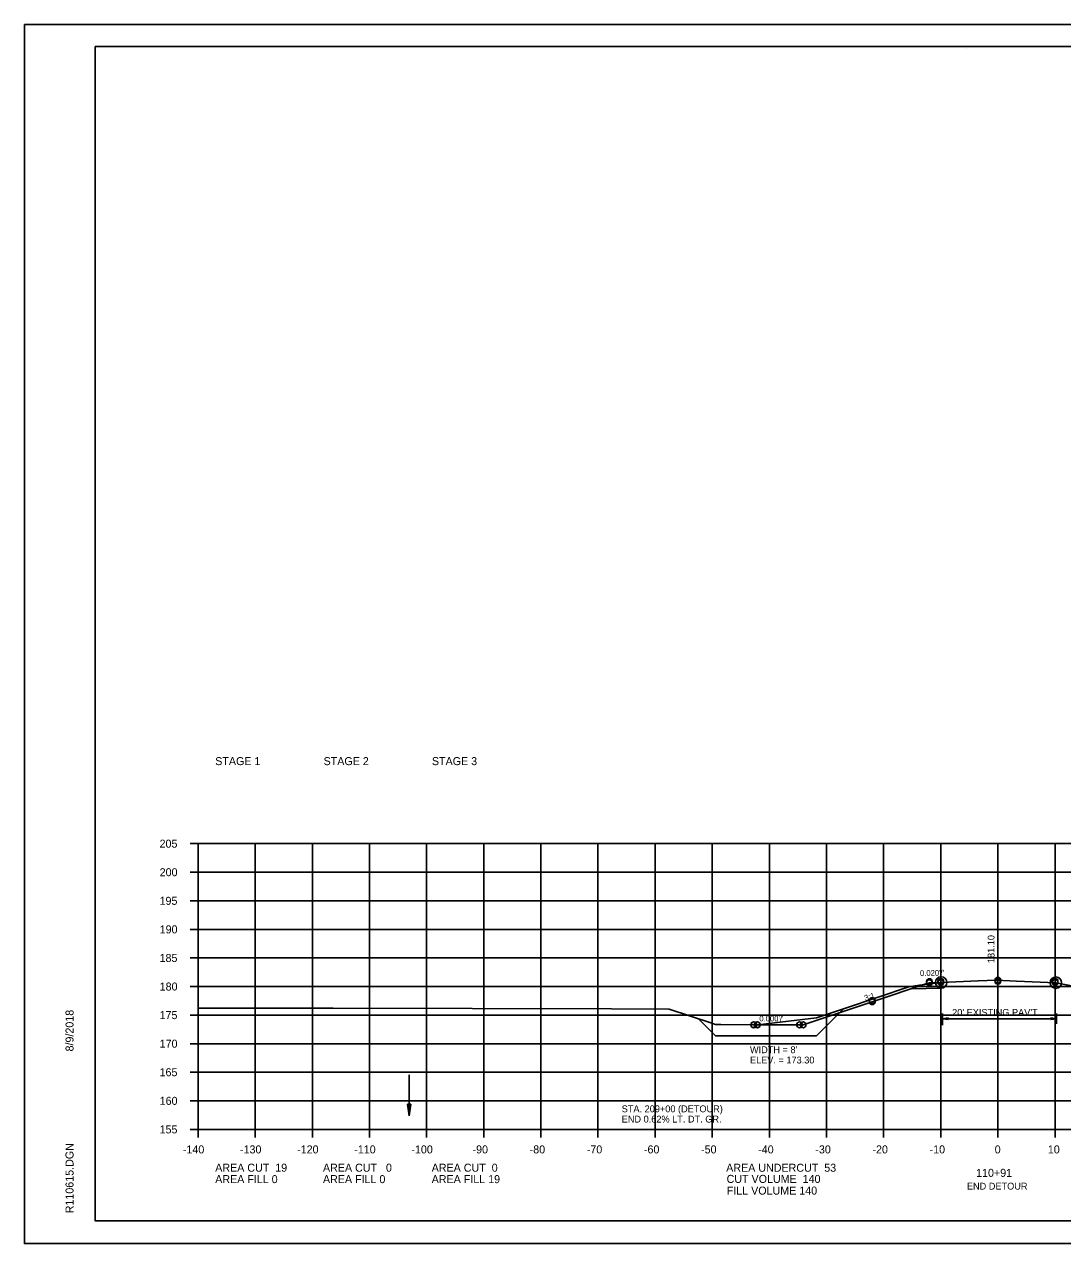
# Model space of a CAD drawing. Extents: x 1372132 to 1372465, y 380083 to 381790.
# Drawn here: x 1372131.6 to 1372313.3, y 381576.9 to 381790.2 of the extents above; entities that cross this region are included whole.
import ezdxf

# ---------------------------------------------------------------- set-up
doc = ezdxf.new("R2010")
doc.units = 0
for name, color, linetype in [('R_Alt Surface', 7, 'Continuous'), ('R_Axis', 7, 'Continuous'), ('R_Axis Annot', 7, 'Continuous'), ('R_Border', 7, 'Continuous'), ('R_Dimension', 7, 'Continuous'), ('R_Draft', 7, 'Continuous'), ('R_Erosion', 7, 'Continuous'), ('R_Exist Surface', 7, 'Continuous'), ('R_Fin Surface', 7, 'Continuous'), ('R_Grid', 7, 'Continuous'), ('R_No Plot', 7, 'Continuous'), ('R_Xsect Elev', 7, 'Continuous'), ('R_Xsect Slope', 7, 'Continuous')]:
    doc.layers.add(name, color=color, linetype=linetype)

msp = doc.modelspace()

# ---------------------------------------------------------------- linework, layer by layer
at = {"layer": 'R_Alt Surface'}
msp.add_lwpolyline([(1372292.07, 381621.55), (1372286.82, 381621.44)], dxfattribs=at)
at = {"layer": 'R_Axis'}
for p, q in [((1372160.61, 381646.84), (1372162.01, 381646.84)), ((1372162.01, 381596.84), (1372162.01, 381646.84)), ((1372160.61, 381641.84), (1372162.01, 381641.84)), ((1372160.61, 381636.84), (1372162.01, 381636.84)), ((1372160.61, 381631.84), (1372162.01, 381631.84)), ((1372160.61, 381626.84), (1372162.01, 381626.84)), ((1372160.61, 381621.84), (1372162.01, 381621.84)), ((1372160.61, 381616.84), (1372162.01, 381616.84)), ((1372160.61, 381611.84), (1372162.01, 381611.84)), ((1372160.61, 381606.84), (1372162.01, 381606.84)), ((1372160.61, 381601.84), (1372162.01, 381601.84)), ((1372160.61, 381596.84), (1372162.01, 381596.84)), ((1372162.01, 381596.84), (1372442.01, 381596.84)), ((1372162.01, 381595.44), (1372162.01, 381596.84)), ((1372172.01, 381595.44), (1372172.01, 381596.84)), ((1372182.01, 381595.44), (1372182.01, 381596.84)), ((1372192.01, 381595.44), (1372192.01, 381596.84)), ((1372202.01, 381595.44), (1372202.01, 381596.84)), ((1372212.01, 381595.44), (1372212.01, 381596.84)), ((1372222.01, 381595.44), (1372222.01, 381596.84)), ((1372232.01, 381595.44), (1372232.01, 381596.84)), ((1372242.01, 381595.44), (1372242.01, 381596.84)), ((1372252.01, 381595.44), (1372252.01, 381596.84)), ((1372262.01, 381595.44), (1372262.01, 381596.84)), ((1372272.01, 381595.44), (1372272.01, 381596.84)), ((1372282.01, 381595.44), (1372282.01, 381596.84)), ((1372292.01, 381595.44), (1372292.01, 381596.84)), ((1372302.01, 381595.44), (1372302.01, 381596.84)), ((1372312.01, 381595.44), (1372312.01, 381596.84))]:
    msp.add_line(p, q, dxfattribs=at)
at = {"layer": 'R_Border'}
for p, q in [((1372144.01, 381786.3), (1372460.19, 381786.3)), ((1372144.01, 381580.84), (1372144.01, 381786.3)), ((1372296.53, 381786.04), (1372296.53, 381786.04)), ((1372296.53, 381786.04), (1372296.53, 381786.04)), ((1372144.01, 381580.84), (1372144.01, 381580.84)), ((1372460.19, 381580.84), (1372144.01, 381580.84))]:
    msp.add_line(p, q, dxfattribs=at)
at = {"layer": 'R_Dimension'}
for p, q in [((1372198.64, 381601.24), (1372198.94, 381599.24)), ((1372199.24, 381601.24), (1372198.64, 381601.24)), ((1372198.64, 381601.24), (1372198.94, 381599.24)), ((1372199.24, 381601.24), (1372198.64, 381601.24)), ((1372198.69, 381601.24), (1372198.94, 381599.58)), ((1372198.69, 381601.24), (1372198.94, 381599.58)), ((1372198.74, 381601.24), (1372198.94, 381599.92)), ((1372198.74, 381601.24), (1372198.94, 381599.92)), ((1372198.79, 381601.24), (1372198.94, 381600.26)), ((1372198.79, 381601.24), (1372198.94, 381600.26)), ((1372198.84, 381601.24), (1372198.94, 381600.59)), ((1372198.84, 381601.24), (1372198.94, 381600.59)), ((1372198.89, 381601.24), (1372198.94, 381600.93)), ((1372198.89, 381601.24), (1372198.94, 381600.93)), ((1372199.24, 381601.24), (1372198.94, 381599.24)), ((1372199.04, 381601.24), (1372198.94, 381600.59)), ((1372199.14, 381601.24), (1372198.94, 381599.92)), ((1372199.19, 381601.24), (1372198.94, 381599.58)), ((1372199.09, 381601.24), (1372198.94, 381600.26)), ((1372198.99, 381601.24), (1372198.94, 381600.93)), ((1372199.24, 381601.24), (1372198.94, 381599.24)), ((1372199.04, 381601.24), (1372198.94, 381600.59)), ((1372199.14, 381601.24), (1372198.94, 381599.92)), ((1372199.19, 381601.24), (1372198.94, 381599.58)), ((1372199.09, 381601.24), (1372198.94, 381600.26)), ((1372198.99, 381601.24), (1372198.94, 381600.93))]:
    msp.add_line(p, q, dxfattribs=at)
at = {"layer": 'R_Draft'}
for p, q in [((1372292.07, 381622.55), (1372292.07, 381621.55)), ((1372292.29, 381617.11), (1372292.29, 381615.1)), ((1372293.29, 381616.35), (1372292.29, 381616.2)), ((1372293.29, 381616.35), (1372292.29, 381616.2)), ((1372312.27, 381616.2), (1372292.29, 381616.2)), ((1372293.29, 381616.05), (1372292.29, 381616.2)), ((1372293.29, 381616.05), (1372292.29, 381616.2)), ((1372293.29, 381616.32), (1372292.46, 381616.2)), ((1372293.29, 381616.32), (1372292.46, 381616.2)), ((1372293.29, 381616.07), (1372292.46, 381616.2)), ((1372293.29, 381616.07), (1372292.46, 381616.2)), ((1372293.29, 381616.3), (1372292.63, 381616.2)), ((1372293.29, 381616.3), (1372292.63, 381616.2)), ((1372293.29, 381616.1), (1372292.63, 381616.2)), ((1372293.29, 381616.1), (1372292.63, 381616.2)), ((1372293.29, 381616.27), (1372292.8, 381616.2)), ((1372293.29, 381616.27), (1372292.8, 381616.2)), ((1372293.29, 381616.12), (1372292.8, 381616.2)), ((1372293.29, 381616.12), (1372292.8, 381616.2)), ((1372293.29, 381616.24), (1372292.97, 381616.2)), ((1372293.29, 381616.24), (1372292.97, 381616.2)), ((1372293.29, 381616.15), (1372292.97, 381616.2)), ((1372293.29, 381616.15), (1372292.97, 381616.2)), ((1372293.29, 381616.22), (1372293.13, 381616.2)), ((1372293.29, 381616.22), (1372293.13, 381616.2)), ((1372293.29, 381616.17), (1372293.13, 381616.2)), ((1372293.29, 381616.17), (1372293.13, 381616.2)), ((1372293.29, 381616.05), (1372293.29, 381616.35)), ((1372293.29, 381616.05), (1372293.29, 381616.35)), ((1372311.27, 381616.35), (1372312.27, 381616.2)), ((1372311.27, 381616.35), (1372311.27, 381616.05)), ((1372311.27, 381616.32), (1372312.11, 381616.2)), ((1372311.27, 381616.3), (1372311.93, 381616.2)), ((1372311.27, 381616.27), (1372311.77, 381616.2)), ((1372311.27, 381616.24), (1372311.6, 381616.2)), ((1372311.27, 381616.22), (1372311.43, 381616.2)), ((1372311.27, 381616.05), (1372312.27, 381616.2)), ((1372311.27, 381616.15), (1372311.6, 381616.2)), ((1372311.27, 381616.1), (1372311.93, 381616.2)), ((1372311.27, 381616.07), (1372312.11, 381616.2)), ((1372311.27, 381616.12), (1372311.77, 381616.2)), ((1372311.27, 381616.17), (1372311.43, 381616.2)), ((1372312.27, 381617.11), (1372312.27, 381615.34)), ((1372292.29, 381615.34), (1372292.29, 381615.34)), ((1372198.94, 381606.38), (1372198.94, 381599.24))]:
    msp.add_line(p, q, dxfattribs=at)
at = {"layer": 'R_Erosion'}
for p, q in [((1372252.56, 381613.22), (1372249.56, 381616.22)), ((1372270.24, 381613.22), (1372274.96, 381617.94)), ((1372252.56, 381613.22), (1372270.24, 381613.22))]:
    msp.add_line(p, q, dxfattribs=at)
at = {"layer": 'R_Exist Surface'}
msp.add_lwpolyline([(1372162.01, 381618.03), (1372185.65, 381618.08), (1372234.35, 381617.93), (1372244.46, 381617.9), (1372251.59, 381615.55), (1372252.57, 381615.22), (1372253.51, 381615.21), (1372260.01, 381615.15), (1372262.93, 381615.47), (1372270.24, 381616.36), (1372275.34, 381618.06), (1372286.43, 381621.81), (1372288.26, 381622.06), (1372292.07, 381622.56), (1372298.54, 381622.82), (1372301.72, 381622.96), (1372305.27, 381622.8), (1372312.16, 381622.51), (1372317.13, 381621.56)], dxfattribs=at)
at = {"layer": 'R_Fin Surface'}
msp.add_lwpolyline([(1372259.87, 381615.15), (1372259.87, 381615.15), (1372259.9, 381615.14), (1372260.27, 381615.14), (1372267.9, 381615.14), (1372268.45, 381615.32), (1372280.01, 381619.18), (1372289.56, 381622.36), (1372290.01, 381622.51), (1372290.1, 381622.51), (1372292.07, 381622.55)], dxfattribs=at)
at = {"layer": 'R_Grid'}
for p, q in [((1372162.01, 381646.84), (1372442.01, 381646.84)), ((1372162.01, 381596.84), (1372162.01, 381646.84)), ((1372172.01, 381596.84), (1372172.01, 381646.84)), ((1372182.01, 381596.84), (1372182.01, 381646.84)), ((1372192.01, 381596.84), (1372192.01, 381646.84)), ((1372202.01, 381596.84), (1372202.01, 381646.84)), ((1372212.01, 381596.84), (1372212.01, 381646.84)), ((1372222.01, 381596.84), (1372222.01, 381646.84)), ((1372232.01, 381596.84), (1372232.01, 381646.84)), ((1372242.01, 381596.84), (1372242.01, 381646.84)), ((1372252.01, 381596.84), (1372252.01, 381646.84)), ((1372262.01, 381596.84), (1372262.01, 381646.84)), ((1372272.01, 381596.84), (1372272.01, 381646.84)), ((1372282.01, 381596.84), (1372282.01, 381646.84)), ((1372292.01, 381596.84), (1372292.01, 381646.84)), ((1372302.01, 381596.84), (1372302.01, 381646.84)), ((1372312.01, 381596.84), (1372312.01, 381646.84)), ((1372162.01, 381641.84), (1372442.01, 381641.84)), ((1372162.01, 381636.84), (1372442.01, 381636.84)), ((1372162.01, 381631.84), (1372442.01, 381631.84)), ((1372162.01, 381626.84), (1372442.01, 381626.84)), ((1372162.01, 381621.84), (1372442.01, 381621.84)), ((1372162.01, 381616.84), (1372442.01, 381616.84)), ((1372162.01, 381611.84), (1372442.01, 381611.84)), ((1372162.01, 381606.84), (1372442.01, 381606.84)), ((1372162.01, 381601.84), (1372442.01, 381601.84)), ((1372162.01, 381596.84), (1372442.01, 381596.84))]:
    msp.add_line(p, q, dxfattribs=at)
at = {"layer": 'R_No Plot'}
for p, q in [((1372131.61, 381790.19), (1372464.95, 381790.19)), ((1372131.61, 381576.86), (1372464.95, 381576.86))]:
    msp.add_line(p, q, dxfattribs=at)
for points in [[(1372131.61, 381790.19), (1372464.95, 381790.19), (1372464.95, 381576.86), (1372131.61, 381576.86)], [(1372377.93, 381786.3), (1372377.93, 381776.42), (1372413.67, 381776.42), (1372413.67, 381773.5), (1372436.87, 381773.5), (1372436.87, 381749.17), (1372460.19, 381749.17), (1372460.19, 381580.84), (1372144.01, 381580.84), (1372144.01, 381786.3)]]:
    msp.add_lwpolyline(points, close=True, dxfattribs=at)
for centre, radius in [((1372290.01, 381622.71), 0.5), ((1372290.01, 381622.51), 0.5), ((1372292.07, 381622.56), 1), ((1372292.01, 381622.75), 0.5), ((1372292.01, 381622.55), 0.5), ((1372302.01, 381622.95), 0.5), ((1372302.01, 381622.75), 0.5), ((1372312.16, 381622.51), 1), ((1372312.01, 381622.75), 0.5), ((1372312.01, 381622.55), 0.5), ((1372280.01, 381619.38), 0.5), ((1372280.01, 381619.18), 0.5), ((1372259.26, 381615.16), 0.5), ((1372259.3, 381615.14), 0.5), ((1372259.87, 381615.15), 0.5), ((1372259.9, 381615.14), 0.5), ((1372267.3, 381615.14), 0.5), ((1372267.9, 381615.14), 0.5)]:
    msp.add_circle(centre, radius, dxfattribs=at)
at = {"layer": 'R_Xsect Elev'}
msp.add_line((1372302.01, 381622.94), (1372302.01, 381632.94), dxfattribs=at)

# ---------------------------------------------------------------- texts
at = {"layer": 'R_Axis Annot'}
for s, p in [('STAGE 1', (1372165.01, 381660.58)), ('STAGE 2', (1372183.98, 381660.58)), ('STAGE 3', (1372202.94, 381660.58)), ('205', (1372155.27, 381646.14)), ('200', (1372155.29, 381641.14)), ('195', (1372155.27, 381636.14)), ('190', (1372155.29, 381631.14)), ('185', (1372155.27, 381626.14)), ('180', (1372155.29, 381621.14)), ('175', (1372155.27, 381616.14)), ('170', (1372155.29, 381611.14)), ('165', (1372155.27, 381606.14)), ('160', (1372155.29, 381601.14)), ('155', (1372155.27, 381596.14)), ('-140', (1372159.35, 381592.64)), ('-130', (1372169.35, 381592.64)), ('-120', (1372179.35, 381592.64)), ('-110', (1372189.35, 381592.64)), ('-100', (1372199.35, 381592.64)), ('-90', (1372210.05, 381592.64)), ('-80', (1372220.05, 381592.64)), ('-70', (1372230.05, 381592.64)), ('-60', (1372240.05, 381592.64)), ('-50', (1372250.05, 381592.64)), ('-40', (1372260.05, 381592.64)), ('-30', (1372270.05, 381592.64)), ('-20', (1372280.05, 381592.64)), ('-10', (1372290.05, 381592.64)), ('0', (1372301.45, 381592.64)), ('10', (1372310.75, 381592.64)), ('AREA CUT  19', (1372165.01, 381589.44)), ('AREA CUT   0', (1372183.87, 381589.44)), ('AREA CUT  0', (1372202.9, 381589.44)), ('AREA UNDERCUT  53', (1372254.45, 381589.43)), ('AREA FILL 0', (1372165.01, 381587.44)), ('AREA FILL 0', (1372183.87, 381587.44)), ('AREA FILL 19', (1372202.9, 381587.44)), ('CUT VOLUME  140', (1372254.52, 381587.48)), ('110+91', (1372298.19, 381588.54)), ('FILL VOLUME 140', (1372254.55, 381585.43))]:
    msp.add_text(s, height=1.4, dxfattribs=at).set_placement(p)
at = {"layer": 'R_Border'}
for s, p in [('8/9/2018', (1372140.21, 381610.48)), ('R110615.DGN', (1372140.21, 381582.16))]:
    msp.add_text(s, height=1.4, rotation=90, dxfattribs=at).set_placement(p)
at = {"layer": 'R_Dimension'}
for s, p in [("WIDTH = 8'", (1372258.61, 381610.18)), ('ELEV. = 173.30', (1372258.61, 381608.38))]:
    msp.add_text(s, height=1.2, dxfattribs=at).set_placement(p)
at = {"layer": 'R_Draft'}
for s, p in [("20' EXISTING PAV'T", (1372294, 381616.71)), ('END DETOUR', (1372296.58, 381586.31))]:
    msp.add_text(s, height=1.2, rotation=360, dxfattribs=at).set_placement(p)
for s, p in [('STA. 209+00 (DETOUR)', (1372236.16, 381599.84)), ('END 0.62% LT. DT. GR.', (1372236.16, 381598.04))]:
    msp.add_text(s, height=1.2, dxfattribs=at).set_placement(p)
at = {"layer": 'R_Xsect Elev'}
msp.add_text('181.10', height=1.2, rotation=90, dxfattribs=at).set_placement((1372301.41, 381625.94))
at = {"layer": 'R_Xsect Slope'}
for s, rotation, p in [("0.020'/'", 1.1458, (1372288.38, 381623.68)), ('3:1', 18.434, (1372278.8, 381619.3)), ("0.000'/'", 0.0001, (1372260.25, 381615.74))]:
    msp.add_text(s, height=1, rotation=rotation, dxfattribs=at).set_placement(p)

doc.saveas('drawing.dxf')
